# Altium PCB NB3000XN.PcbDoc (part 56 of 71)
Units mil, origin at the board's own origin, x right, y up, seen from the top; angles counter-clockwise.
Board outline 9527.56 x 6929.77 mil, 6 copper layers (Top Layer, GND+SHIELD, MidLayer1, MidLayer2, P2 - 3V3+5V0, Bottom Layer), stack 62.375 mil thick; 832 components, 1027 nets, 4655 pads, 4981 vias.
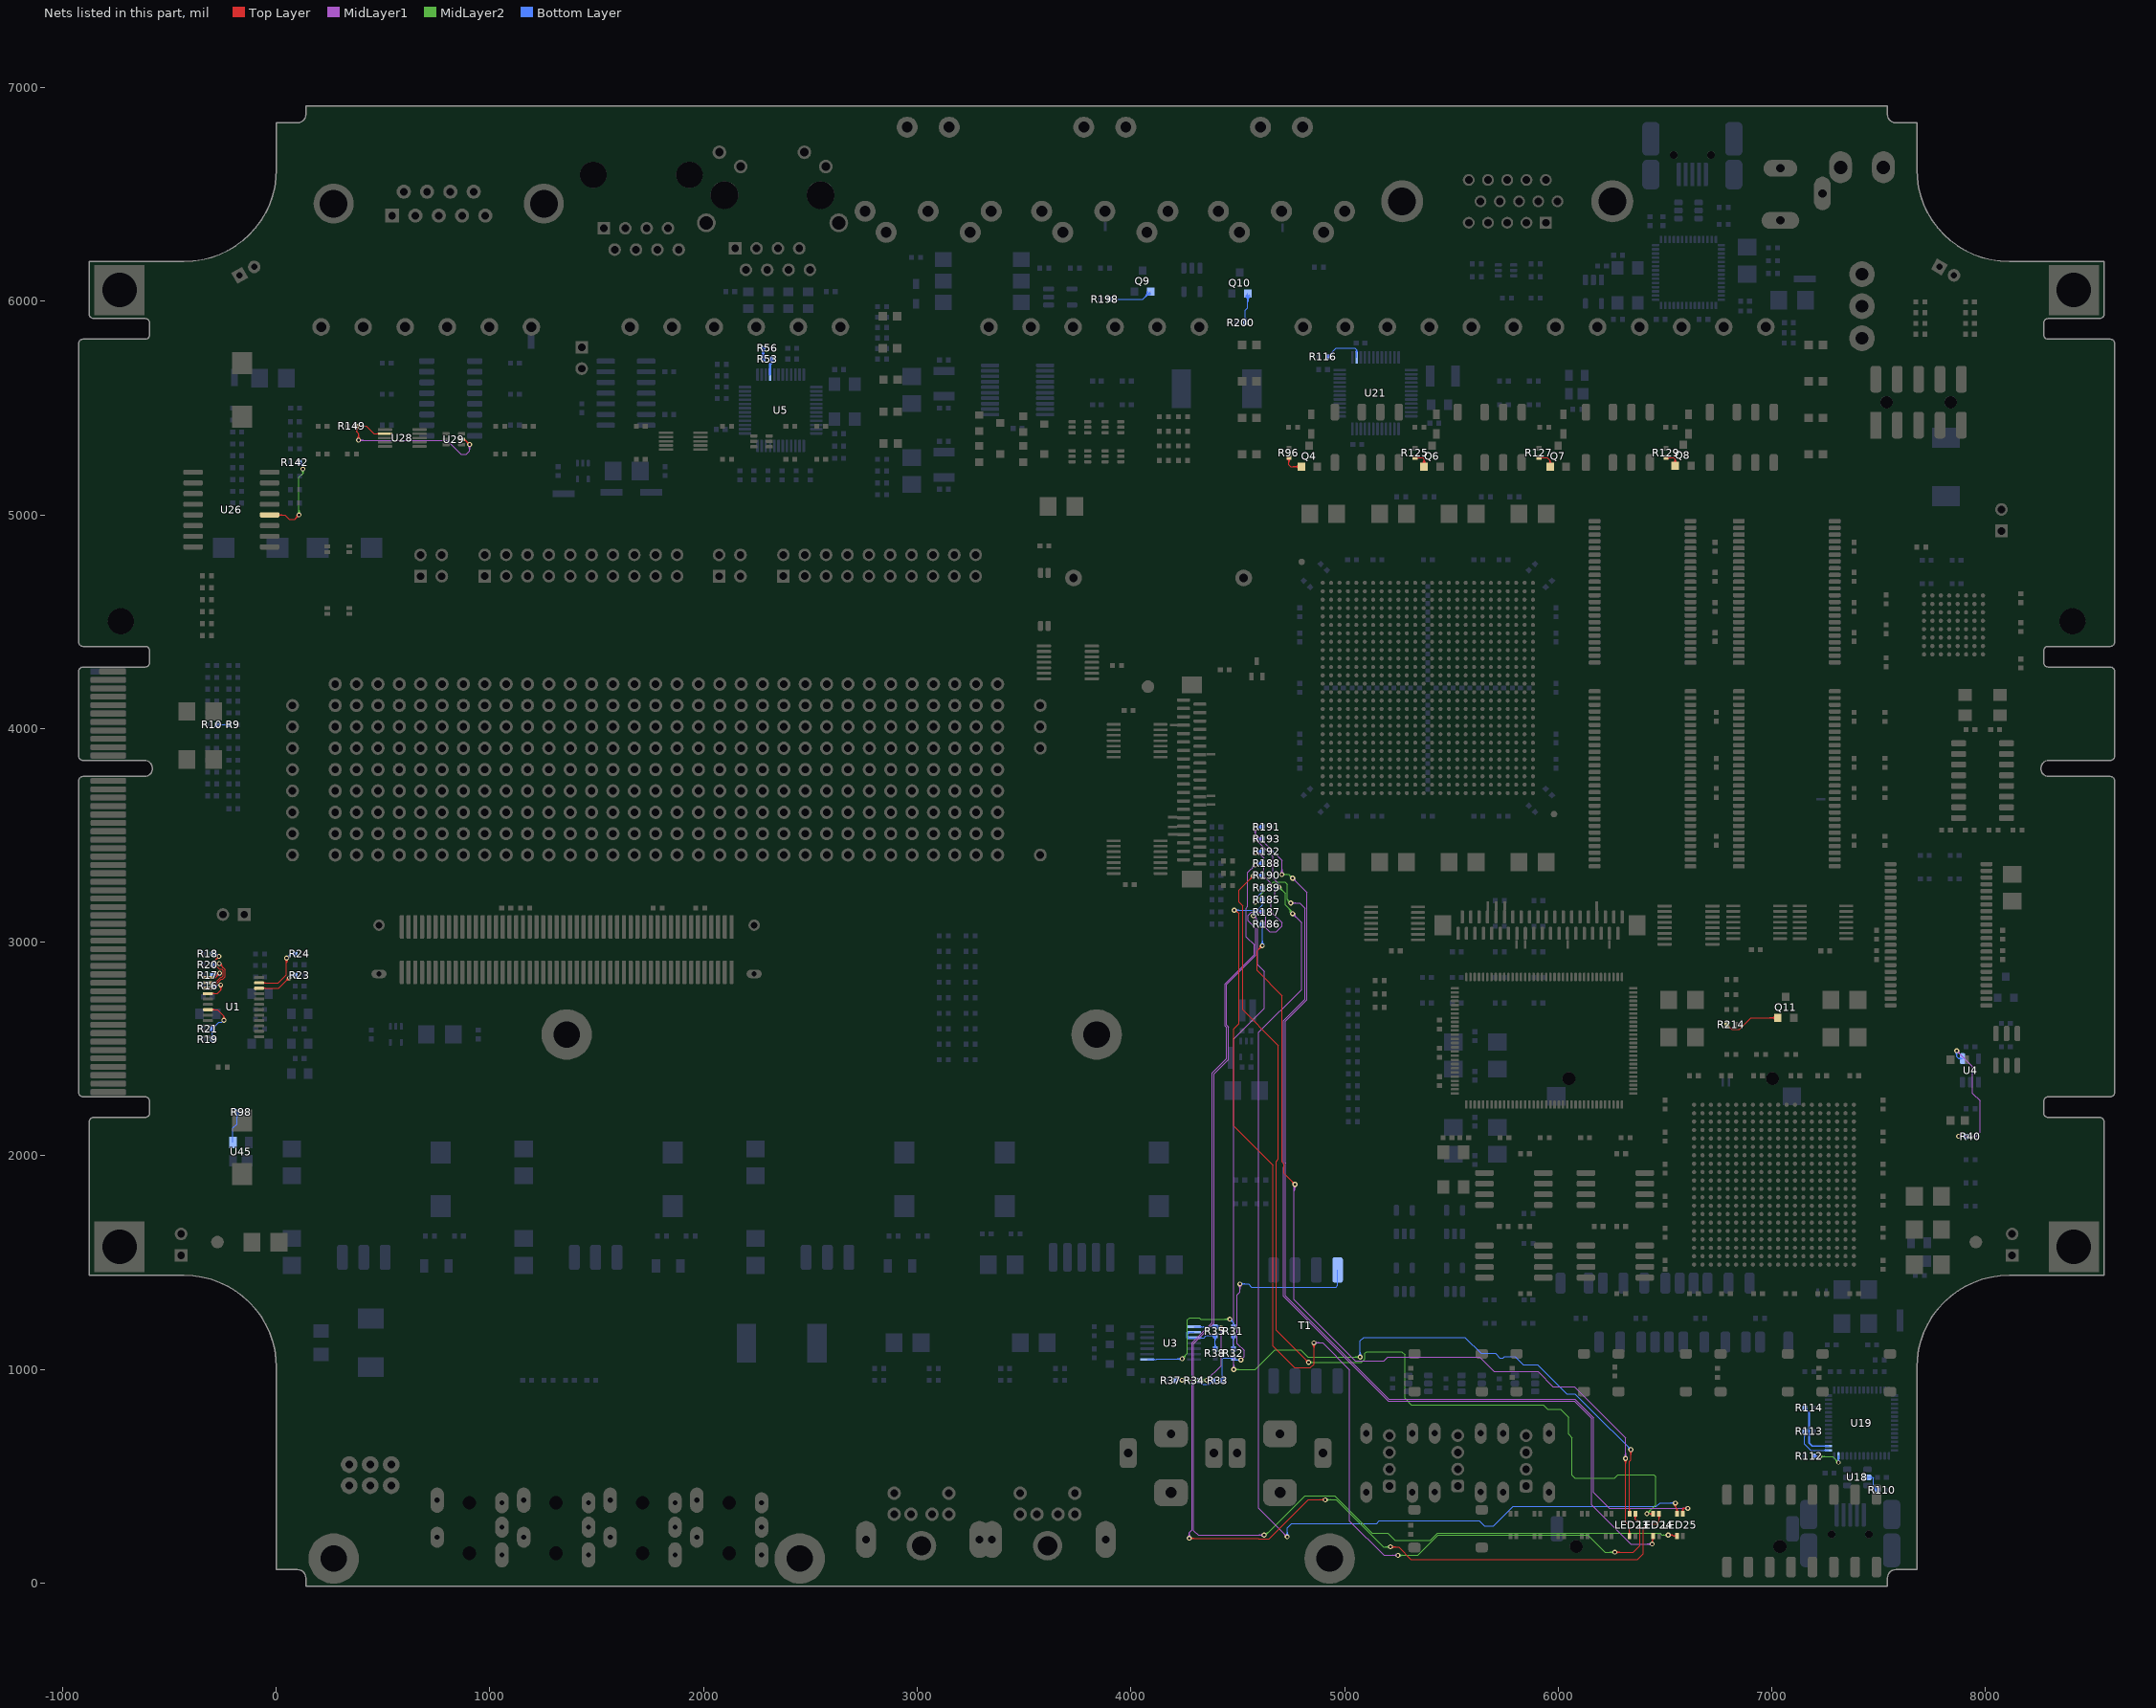
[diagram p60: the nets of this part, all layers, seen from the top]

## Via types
v1: diameter 23, hole 11.81, Top Layer to Bottom Layer, 3672 vias
v2: diameter 26, hole 11.81, Top Layer to Bottom Layer, 461 vias
v3: diameter 19, hole 11.81, Top Layer to Bottom Layer, tented both sides, 396 vias
v4: diameter 23.62, hole 11.81, Top Layer to Bottom Layer, 288 vias
v5: diameter 20, hole 11.81, Top Layer to Bottom Layer, 91 vias
v6: diameter 23, hole 11.81, Top Layer to Bottom Layer, tented both sides, 50 vias
v7: diameter 31, hole 11.81, Top Layer to Bottom Layer, 15 vias
v8: diameter 27.56, hole 11.81, Top Layer to Bottom Layer, tented both sides, 4 vias
v9: diameter 29, hole 11.81, Top Layer to Bottom Layer, 3 vias
v10: diameter 21, hole 11.81, Top Layer to Bottom Layer, 1 vias

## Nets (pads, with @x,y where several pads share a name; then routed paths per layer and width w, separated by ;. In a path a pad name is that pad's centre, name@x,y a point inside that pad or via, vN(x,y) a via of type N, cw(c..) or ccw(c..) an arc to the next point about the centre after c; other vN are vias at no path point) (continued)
NetLED23_1: LED23.1 R185.1 | length 5760.9
  Top Layer w4: v1(4483.52,3150.04) 4490.19,3150.04 4507.19,3133.04 4507.19,2620.02 4481.86,2594.69 4481.86,2138.73 4664.71,1955.87 4664.71,1108.85 4765.19,1008.37 4840.19,1008.37 4856.86,1025.04 v1(4856.86,1125.04) ; v1@4483.55,3148.54 cw(c4483.89,3129.71) 4497.2,3143.03 ; v1@4483.62,3144.54 cw(c4484.12,3116.63) 4503.86,3136.37 ; v1@4493.02,3150.04 ccw(c4499.87,3150.04) 4495.03,3145.2 ; v1@4850.14,1118.32 cw(c4833.92,1102.11) 4856.86,1102.11 cw(c4879.79,1102.11) v1@4863.57,1118.32 ; v1@4852.97,1121.15 cw(c4843.58,1111.76) 4856.86,1111.76 cw(c4870.14,1111.76) v1@4860.75,1121.15 ; v1(6265,145) 6351.86,145 6381.86,175 6381.86,285 6371.86,295 6365,295 6360.79,299.21 LED23.1@6360.79,324.21 ; v1@6268.89,141.11 cw(c6278.28,131.72) 6278.28,145 cw(c6278.28,158.28) v1@6268.89,148.89 ; v1@6271.72,138.28 cw(c6287.93,122.06) 6287.93,145 cw(c6287.93,167.93) v1@6271.72,151.72 ; LED23.1@6355.94,314.44 cw(c6344.23,302.73) 6360.79,302.73 cw(c6377.35,302.73) LED23.1@6365.64,314.44
  MidLayer1 w4: v1(4856.86,1125.04) 4897.92,1125.04 5024.19,998.77 5024.19,290.81 5185,130 v1(5250,130) ; v1@4860.75,1121.15 cw(c4870.14,1111.76) 4870.14,1125.04 cw(c4870.14,1138.32) v1@4860.75,1128.93 ; v1@4863.57,1118.32 cw(c4879.79,1102.11) 4879.79,1125.04 cw(c4879.79,1147.98) v1@4863.57,1131.76 ; v1@5243.28,123.28 ccw(c5227.06,107.06) 5227.06,130 ccw(c5227.06,152.93) v1@5243.28,136.72 ; v1@5246.11,126.11 ccw(c5236.72,116.72) 5236.72,130 ccw(c5236.72,143.28) v1@5246.11,133.89
  MidLayer2 w4: v1(5250,130) 5342.78,130 5438.48,225.71 6139.29,225.71 6220,145 v1(6265,145) ; v1@5253.89,126.11 cw(c5263.28,116.72) 5263.28,130 cw(c5263.28,143.28) v1@5253.89,133.89 ; v1@5256.72,123.28 cw(c5272.93,107.06) 5272.93,130 cw(c5272.93,152.93) v1@5256.72,136.72 ; v1@6258.28,138.28 ccw(c6242.06,122.06) 6242.06,145 ccw(c6242.06,167.93) v1@6258.28,151.72 ; v1@6261.11,141.11 ccw(c6251.72,131.72) 6251.72,145 ccw(c6251.72,158.28) v1@6261.11,148.89
  Bottom Layer w4: v1(4483.52,3150.04) 4590.19,3150.04 4615.19,3175.04 ; v1@4487.41,3146.15 cw(c4496.8,3136.76) 4496.8,3150.04 cw(c4496.8,3163.32) v1@4487.41,3153.93 ; v1@4490.24,3143.32 cw(c4506.46,3127.11) 4506.46,3150.04 cw(c4506.46,3172.98) v1@4490.24,3156.76 ; R185.1@4607.75,3191.19 cw(c4593.87,3175) 4615.19,3175 ; R185.1@4610.36,3194.22 cw(c4601.33,3183.7) 4615.19,3183.7 ; R185.1@4613.82,3198.75 4613.82,3200.04 R185.1@4615.19,3200.04 ; 4615.19,3179.07 cw(c4633.01,3179.07) R185.1@4620.41,3191.67 ; R185.1@4615.19,3198.75 4615.19,3175.04
NetLED23_3: LED23.3 R186.1 | length 4572.2
  Top Layer w4: v1@4605.69,2983.37 cw(c4582.76,2983.37) 4598.97,2967.16 cw(c4615.19,2950.94) v1@4615.19,2973.87 ; v1@4609.69,2983.37 cw(c4596.41,2983.37) 4605.8,2973.99 cw(c4615.19,2964.6) v1@4615.19,2977.87 ; v1(4615.19,2983.37) 4590.19,2958.37 4590.19,2866.71 4706.86,2750.04 4706.86,1971.86 4716.34,1962.38 4716.34,1918.56 v1(4768.19,1866.71) ; v1@4758.69,1866.71 ccw(c4735.76,1866.71) 4751.97,1882.93 ccw(c4768.19,1899.14) v1@4768.19,1876.21 ; v1@4762.69,1866.71 ccw(c4749.41,1866.71) 4758.8,1876.1 ccw(c4768.19,1885.49) v1@4768.19,1872.21 ; v1@6308.47,576.66 cw(c6292.26,560.44) 6315.19,560.44 cw(c6338.13,560.44) v1@6321.91,576.66 ; v1@6311.3,579.49 cw(c6301.91,570.1) 6315.19,570.1 cw(c6328.47,570.1) v1@6319.08,579.49 ; v1(6315.19,583.37) 6315.19,285 6333.59,266.6 LED23.3@6333.59,220.81 ; LED23.3@6328.74,230.58 ccw(c6317.03,242.29) 6333.59,242.29 ccw(c6350.15,242.29) LED23.3@6338.44,230.58
  MidLayer1 w4: v1@4761.47,1859.99 cw(c4753.69,1852.21) 4764.7,1852.21 ; 4764.7,1835.34 cw(c4799.56,1835.34) v1@4774.91,1859.99 ; 4764.7,1844.99 cw(c4789.9,1844.99) v1@4772.08,1862.82 ; 4764.7,1854.65 cw(c4780.25,1854.65) v1@4769.25,1865.65 ; v1(4768.19,1866.71) 4764.7,1863.21 4764.7,1326.14 5049.96,1040.87 5185.69,1040.87 5202.62,1057.81 5632.19,1057.81 5700,990 5905,990 5975,920 6075,920 6314.69,680.31 6314.69,583.87 v1(6315.19,583.37) ; v1@6308.47,590.09 ccw(c6293.46,605.1) 6314.69,605.1 ; v1@6311.3,587.26 ccw(c6303.12,595.45) 6314.69,595.45 ; 6314.69,597.86 ccw(c6329.68,597.86) v1@6319.08,587.26 ; 6314.69,607.52 ccw(c6339.33,607.52) v1@6321.91,590.09
  Bottom Layer w4: R186.1@4607.23,3077.92 cw(c4588.01,3058.7) 4615.19,3058.7 ; v1@4608.47,2990.09 ccw(c4592.26,3006.31) 4615.19,3006.31 ccw(c4638.13,3006.31) v1@4621.91,2990.09 ; R186.1@4610.06,3080.75 cw(c4597.67,3068.36) 4615.19,3068.36 ; v1@4611.3,2987.26 ccw(c4601.91,2996.65) 4615.19,2996.65 ccw(c4628.47,2996.65) v1@4619.08,2987.26 ; R186.1@4613.82,3085 4613.82,3084.51 4615.19,3084.51 v1(4615.19,2983.37) ; 4615.19,3065.32 cw(c4633.01,3065.32) R186.1@4620.41,3077.92
NetLED23_4: LED23.4 R187.1 | length 5308.4
  Top Layer w4: LED23.4@6328.84,333.98 ccw(c6317.81,345.01) 6333.41,345.01 ; LED23.4@6333.41,321.33 6333.41,570 6340.19,576.78 v1(6340.19,625.04) ; 6333.41,346.36 ccw(c6350.92,346.36) LED23.4@6338.54,333.98 ; v1@6333.47,618.32 cw(c6317.26,602.11) 6340.19,602.11 cw(c6363.13,602.11) v1@6346.91,618.32 ; v1@6336.3,621.15 cw(c6326.91,611.76) 6340.19,611.76 cw(c6353.47,611.76) v1@6344.08,621.15
  MidLayer1 w4: v1@4475.14,1006.76 ccw(c4458.92,1022.98) 4481.86,1022.98 ccw(c4504.79,1022.98) v1@4488.57,1006.76 ; v1@4477.97,1003.93 ccw(c4468.58,1013.32) 4481.86,1013.32 ccw(c4495.14,1013.32) v1@4485.75,1003.93 ; v1(4481.86,1000.04) 4481.86,2547.67 4623.86,2689.67 4623.86,2864.04 4593.19,2894.71 4593.19,3104.04 v1(4573.52,3123.71) ; v1@4573.52,3114.21 cw(c4573.52,3091.27) 4589.74,3107.49 cw(c4605.96,3123.71) v1@4583.02,3123.71 ; v1@4573.52,3118.21 cw(c4573.52,3104.93) 4582.91,3114.32 cw(c4592.3,3123.71) v1@4579.02,3123.71
  MidLayer2 w4: v1(4481.86,1000.04) 4583.19,1000.04 4674.86,1091.71 4795.54,1091.71 4828.88,1058.37 v1(5073.52,1058.37) ; v1@4485.75,996.15 cw(c4495.14,986.76) 4495.14,1000.04 cw(c4495.14,1013.32) v1@4485.75,1003.93 ; v1@4488.57,993.32 cw(c4504.79,977.11) 4504.79,1000.04 cw(c4504.79,1022.98) v1@4488.57,1006.76 ; v1@5066.81,1051.66 ccw(c5050.59,1035.44) 5050.59,1058.37 ccw(c5050.59,1081.31) v1@5066.81,1065.09 ; v1@5069.64,1054.49 ccw(c5060.25,1045.1) 5060.25,1058.37 ccw(c5060.25,1071.65) v1@5069.64,1062.26
  Bottom Layer w4: v1(4573.52,3123.71) 4591.69,3141.87 ; v1@4573.52,3129.21 ccw(c4573.52,3142.49) 4582.91,3133.1 ccw(c4592.3,3123.71) v1@4579.02,3123.71 ; v1@4573.52,3133.21 ccw(c4573.52,3156.14) 4589.74,3139.93 ccw(c4605.96,3123.71) v1@4583.02,3123.71 ; R187.1@4607.15,3135.36 ccw(c4591.69,3120.26) 4591.69,3141.87 ; R187.1@4607.15,3148.39 cw(c4591.69,3163.48) 4591.69,3141.87 ; R187.1@4610.01,3138.16 ccw(c4601.19,3129.54) 4601.19,3141.87 ccw(c4601.19,3154.21) R187.1@4610.01,3145.59 ; R187.1@4613.82,3141.88 4591.69,3141.87 ; v1@5066.81,1065.09 ccw(c5050.59,1081.31) 5073.52,1081.31 ccw(c5096.46,1081.31) v1@5080.24,1065.09 ; v1@5069.64,1062.26 ccw(c5060.25,1071.65) 5073.52,1071.65 ccw(c5086.8,1071.65) v1@5077.41,1062.26 ; v1(5073.52,1058.37) 5073.52,1133.52 5090,1150 5564.02,1150 5639.02,1075 5705.79,1075 5727.75,1053.04 5742.25,1053.04 5749.43,1060.22 5798.44,1060.22 5835.66,1023 5903.31,1023 6039.86,886.46 6078.78,886.46 6156.86,808.37 v1(6340.19,625.04) ; v1@6330.69,625.04 ccw(c6307.76,625.04) 6323.97,641.26 ccw(c6340.19,657.48) v1@6340.19,634.54 ; v1@6334.69,625.04 ccw(c6321.41,625.04) 6330.8,634.43 ccw(c6340.19,643.82) v1@6340.19,630.54
NetLED24_1: LED24.1 R188.1 | length 6494.6
  Top Layer w4: v1(4273.52,210) 4595,210 4598.57,206.43 4646.58,206.43 4830.15,390 v4(4910,390) ; v1@4277.41,206.11 cw(c4286.8,196.72) 4286.8,210 cw(c4286.8,223.28) v1@4277.41,213.89 ; v1@4280.24,203.28 cw(c4296.46,187.06) 4296.46,210 cw(c4296.46,232.93) v1@4280.24,216.72 ; v4@4903.06,383.06 ccw(c4886.31,366.31) 4886.31,390 ccw(c4886.31,413.69) v4@4903.06,396.94 ; v4@4905.89,385.89 ccw(c4895.97,375.97) 4895.97,390 ccw(c4895.97,404.03) v4@4905.89,394.11 ; v4(5215,170) 5253.14,170 5311.14,112 6372,112 6398.19,138.19 6398.19,258.19 6417.07,277.07 6458.89,277.07 6472.22,290.4 LED24.1@6472.22,321.33 ; v4@5219.11,165.89 cw(c5229.03,155.97) 5229.03,170 cw(c5229.03,184.03) v4@5219.11,174.11 ; v4@5221.94,163.06 cw(c5238.69,146.31) 5238.69,170 cw(c5238.69,193.69) v4@5221.94,176.94 ; LED24.1@6467.19,314.44 cw(c6455.05,302.3) 6472.22,302.3 ; 6472.22,303.16 cw(c6488.16,303.16) LED24.1@6476.89,314.44
  MidLayer1 w4: v1@4266.81,216.72 ccw(c4250.59,232.93) 4273.52,232.93 ccw(c4296.46,232.93) v1@4280.24,216.72 ; v1@4269.64,213.89 ccw(c4260.25,223.28) 4273.52,223.28 ccw(c4286.8,223.28) v1@4277.41,213.89 ; v1(4273.52,210) 4273.52,236.9 4286,249.37 4286,1124.69 4381.52,1220.21 4381.52,2388 4448.52,2455 4448.52,2600.04 4440.19,2608.37 4440.19,2804.71 4577.19,2941.71 4577.19,2988.04 4540.19,3025.04 4540.19,3159.71 4547.19,3166.71 4547.19,3326.37 v1(4581.86,3361.04) ; v1@4572.36,3361.04 cw(c4549.42,3361.04) 4565.64,3344.82 cw(c4581.86,3328.61) v1@4581.86,3351.54 ; v1@4576.36,3361.04 cw(c4563.08,3361.04) 4572.47,3351.65 cw(c4581.86,3342.26) v1@4581.86,3355.54
  MidLayer2 w4: v4(4910,390) 4961.55,390 5181.55,170 v4(5215,170) ; v4@4914.11,385.89 cw(c4924.03,375.97) 4924.03,390 cw(c4924.03,404.03) v4@4914.11,394.11 ; v4@4916.94,383.06 cw(c4933.69,366.31) 4933.69,390 cw(c4933.69,413.69) v4@4916.94,396.94 ; v4@5208.06,163.06 ccw(c5191.31,146.31) 5191.31,170 ccw(c5191.31,193.69) v4@5208.06,176.94 ; v4@5210.89,165.89 ccw(c5200.97,155.97) 5200.97,170 ccw(c5200.97,184.03) v4@5210.89,174.11
  Bottom Layer w4: v1@4579.73,3362.35 cw(c4592.31,3354.59) 4592.31,3369.37 ; v1(4581.86,3361.04) 4590.19,3369.37 R188.1@4613.82,3369.38 ccw(c4613.82,3341.32) v1@4589.94,3356.05 ; v1@4583.13,3360.25 cw(c4599.48,3350.17) 4599.48,3369.37 ; v1@4586.54,3358.15 cw(c4606.65,3345.74) R188.1@4606.65,3369.37 ; R188.1@4607.23,3362.79 ccw(c4591.32,3346.88) 4591.32,3369.37 ccw(c4591.32,3391.87) R188.1@4607.23,3375.96 ; R188.1@4610.06,3365.61 ccw(c4600.98,3356.53) 4600.98,3369.37 ccw(c4600.98,3382.22) R188.1@4610.06,3373.14
NetLED24_3: LED24.3 R189.1 | length 5102.6
  Top Layer w4: v1@6436.3,187.26 ccw(c6426.91,196.65) 6440.19,196.65 ccw(c6453.47,196.65) v1@6444.08,187.26 ; v1(6440.19,183.37) 6440.19,200 6444.84,204.65 ; LED24.3@6441.7,209.79 cw(c6439.06,204.65) 6444.84,204.65 ; LED24.3@6443.31,222.34 LED24.3@6444.66,223.69 ; LED24.3@6444.84,220.81 6444.84,204.65 ; LED24.3@6447.97,209.79 ccw(c6450.62,204.65) 6444.84,204.65
  MidLayer1 w4: v1(4748.52,3183.37) 4790.52,3183.37 4815.52,3158.37 4815.52,2733.37 4715.19,2633.04 4715.19,1963.52 4716.34,1962.38 4716.34,1947.62 4715.19,1946.48 4715.19,1341.71 5095.75,961.15 5204.9,852 6075.37,852 6156.86,770.52 6156.86,366.71 6340.19,183.37 v1(6440.19,183.37) ; v1@4752.41,3179.49 cw(c4761.8,3170.1) 4761.8,3183.37 cw(c4761.8,3196.65) v1@4752.41,3187.26 ; v1@4755.24,3176.66 cw(c4771.46,3160.44) 4771.46,3183.37 cw(c4771.46,3206.31) v1@4755.24,3190.09 ; v1@6433.47,176.66 ccw(c6417.26,160.44) 6417.26,183.37 ccw(c6417.26,206.31) v1@6433.47,190.09 ; v1@6436.3,179.49 ccw(c6426.91,170.1) 6426.91,183.37 ccw(c6426.91,196.65) v1@6436.3,187.26
  MidLayer2 w4: v1(4581.86,3187.37) 4609.24,3214.75 4609.24,3223.11 4668.5,3282.37 4720.21,3282.37 4731.52,3271.06 4731.52,3200.37 v1(4748.52,3183.37) ; v1@4581.86,3192.87 ccw(c4581.86,3206.15) 4591.25,3196.76 ccw(c4600.64,3187.37) v1@4587.36,3187.37 ; v1@4581.86,3196.87 ccw(c4581.86,3219.81) 4598.07,3203.59 ccw(c4614.29,3187.37) v1@4591.36,3187.37 ; v1@4739.02,3183.37 ccw(c4716.09,3183.37) 4732.31,3199.59 ccw(c4748.52,3215.81) v1@4748.52,3192.87 ; v1@4743.02,3183.37 ccw(c4729.75,3183.37) 4739.14,3192.76 ccw(c4748.52,3202.15) v1@4748.52,3188.87
  Bottom Layer w4: v1@4577.1,3195.6 ccw(c4572.32,3203.85) 4581.86,3203.85 ; v1(4581.86,3187.37) 4581.86,3203.85 ; v1@4586.62,3195.6 cw(c4591.4,3203.85) 4581.86,3203.85 ; R189.1@4608.02,3247.84 cw(c4598.46,3235.81) 4613.82,3235.81 ; R189.1@4613.82,3255.62 4613.82,3235.81 ; R189.1@4619.62,3247.84 ccw(c4629.18,3235.81) 4613.82,3235.81 ; 4581.86,3203.85 4613.82,3235.81
NetLED24_4: LED24.4 R190.1 | length 5308.6
  Top Layer w4: v1@4564.02,3310.04 cw(c4541.09,3310.04) 4557.31,3293.82 cw(c4573.52,3277.61) v1@4573.52,3300.54 ; v1@4568.02,3310.04 cw(c4554.75,3310.04) 4564.14,3300.65 cw(c4573.52,3291.26) v1@4573.52,3304.54 ; v1(4573.52,3310.04) 4506.52,3243.04 4506.52,3188.04 4523.52,3171.04 4523.52,2683.37 4669.72,2537.18 4690.52,2516.37 4690.52,1984.48 4680.71,1974.66 4680.71,1184.52 v1(4831.86,1033.37) ; v1@4822.36,1033.37 ccw(c4799.42,1033.37) 4815.64,1049.59 ccw(c4831.86,1065.81) v1@4831.86,1042.87 ; v1@4826.36,1033.37 ccw(c4813.08,1033.37) 4822.47,1042.76 ccw(c4831.86,1052.15) v1@4831.86,1038.87 ; v1(6415.19,325.04) 6429.96,325.04 6430.79,324.21 ; LED24.4@6439.55,319.96 ccw(c6430.79,313.05) 6430.79,324.21 ; LED24.4@6439.55,328.45 cw(c6430.79,335.36) 6430.79,324.21 ; LED24.4@6444.94,324.21 6430.79,324.21
  MidLayer2 w4: v1(4831.86,1033.37) 5080,1033.37 5095,1048.37 5095,1075 5103.37,1083.37 5267.56,1083.37 5282.19,1068.75 5282.19,864.67 5311.98,834.87 5930.13,834.87 5950,815 6010,815 6048.65,776.35 6048.65,696.54 6065.19,680 6065.19,505.04 6078.52,491.71 6263.86,491.71 6280.52,508.37 6446.86,508.37 6456.86,498.37 6456.86,366.71 v1(6415.19,325.04) ; v1@4835.75,1029.49 cw(c4845.14,1020.1) 4845.14,1033.37 cw(c4845.14,1046.65) v1@4835.75,1037.26 ; v1@4838.57,1026.66 cw(c4854.79,1010.44) 4854.79,1033.37 cw(c4854.79,1056.31) v1@4838.57,1040.09 ; 6424.58,334.43 cw(c6415.19,343.82) 6415.19,330.54 ccw(c6415.19,343.82) 6424.58,334.43 ; 6424.58,334.43 ccw(c6433.97,325.04) 6420.69,325.04 cw(c6433.97,325.04) 6424.58,334.43 ; 6431.41,341.26 cw(c6415.19,357.48) 6415.19,334.54 ccw(c6415.19,357.48) 6431.41,341.26 ; 6431.41,341.26 ccw(c6447.63,325.04) 6424.69,325.04 cw(c6447.63,325.04) 6431.41,341.26
  Bottom Layer w4: v1(4573.52,3310.04) 4580.19,3310.04 4582.65,3312.5 R190.1@4613.82,3312.5 ; v1@4577.41,3306.15 cw(c4592.74,3290.83) 4592.74,3312.5 ; v1@4580.24,3303.32 cw(c4602.4,3281.17) 4602.4,3312.5 ; v1@4580.24,3316.76 ccw(c4590.52,3327.04) 4590.52,3312.5 ; R190.1@4607.23,3305.91 ccw(c4591.32,3290) 4591.32,3312.5 ccw(c4591.32,3335) R190.1@4607.23,3319.09 ; R190.1@4610.06,3308.74 ccw(c4600.98,3299.66) 4600.98,3312.5 ccw(c4600.98,3325.34) R190.1@4610.06,3316.26
NetLED25_1: LED25.1 R191.1 | length 5492.9
  Top Layer w4: LED25.1@6578.43,333.98 ccw(c6566.73,345.69) 6583.28,345.69 ccw(c6599.84,345.69) LED25.1@6588.13,333.98 ; LED25.1@6583.28,324.21 6583.28,348.19 6585.13,350.04 ; v1@6599.88,343.59 ccw(c6585.13,329.95) 6585.13,350.04 ; v1@6599.88,356.49 cw(c6585.13,370.13) 6585.13,350.04 ; v1@6602.82,346.31 ccw(c6594.28,338.41) 6594.28,350.04 ccw(c6594.28,361.67) v1@6602.82,353.78 ; v1(6606.86,350.04) 6585.13,350.04
  MidLayer1 w4: v1@4575.14,3525.66 cw(c4558.92,3509.44) 4581.86,3509.44 cw(c4604.79,3509.44) v1@4588.57,3525.66 ; v1@4577.97,3528.49 cw(c4568.58,3519.1) 4581.86,3519.1 cw(c4595.14,3519.1) v1@4585.75,3528.49 ; v1(4581.86,3532.37) 4581.86,3508.37 4706.86,3383.37 v1(4706.86,3316.71) ; v1@4700.14,3323.43 ccw(c4683.92,3339.64) 4706.86,3339.64 ccw(c4729.79,3339.64) v1@4713.57,3323.43 ; v1@4702.97,3320.6 ccw(c4693.58,3329.99) 4706.86,3329.99 ccw(c4720.14,3329.99) v1@4710.75,3320.6 ; v1@4756.86,3290.54 cw(c4756.86,3267.61) 4773.07,3283.82 cw(c4789.29,3300.04) v1@4766.36,3300.04 ; v1@4756.86,3294.54 cw(c4756.86,3281.26) 4766.25,3290.65 cw(c4775.64,3300.04) v1@4762.36,3300.04 ; v1(4756.86,3300.04) 4823.52,3233.37 4823.52,2730.06 4723.19,2629.73 4723.19,1966.84 4724.34,1965.69 4724.34,1944.31 4723.19,1943.16 4723.19,1345.02 5208.21,860 6078.69,860 6165.19,773.5 6165.19,425.04 6240.19,350.04 v1(6606.86,350.04) ; v1@6600.14,343.32 ccw(c6583.92,327.11) 6583.92,350.04 ccw(c6583.92,372.98) v1@6600.14,356.76 ; v1@6602.97,346.15 ccw(c6593.58,336.76) 6593.58,350.04 ccw(c6593.58,363.32) v1@6602.97,353.93
  MidLayer2 w4: v1(4706.86,3316.71) 4740.19,3316.71 v1(4756.86,3300.04) ; v1@4710.75,3312.82 cw(c4720.14,3303.43) 4720.14,3316.71 cw(c4720.14,3329.99) v1@4710.75,3320.6 ; v1@4713.57,3309.99 cw(c4729.79,3293.77) 4729.79,3316.71 cw(c4729.79,3339.64) v1@4713.57,3323.43 ; v1@4747.36,3300.04 ccw(c4724.42,3300.04) 4740.64,3316.26 ccw(c4756.86,3332.48) v1@4756.86,3309.54 ; v1@4751.36,3300.04 ccw(c4738.08,3300.04) 4747.47,3309.43 ccw(c4756.86,3318.82) v1@4756.86,3305.54
  Bottom Layer w4: v1@4579.78,3533.76 cw(c4591.42,3526.01) 4591.42,3540 ; v1(4581.86,3532.37) 4581.86,3533.37 4588.48,3540 R191.1@4613.82,3540 ccw(c4613.82,3511.11) v1@4589.77,3527.11 ; v1@4583.11,3531.54 cw(c4598.89,3521.05) 4598.89,3540 ; v1@4586.44,3529.33 cw(c4606.35,3516.08) R191.1@4606.35,3540 ; R191.1@4607.23,3533.41 ccw(c4591.32,3517.5) 4591.32,3540 ccw(c4591.32,3562.5) R191.1@4607.23,3546.59 ; R191.1@4610.06,3536.24 ccw(c4600.98,3527.16) 4600.98,3540 ccw(c4600.98,3552.84) R191.1@4610.06,3543.76
NetLED25_3: LED25.3 R192.1 | length 6560.1
  Top Layer w4: v1(6515.19,225.04) 6535,225.04 ; v1@6522.6,219.09 cw(c6535,209.14) 6535,225.04 ; v1@6522.6,230.99 ccw(c6535,240.94) 6535,225.04 ; 6536.35,223.69 6535,225.04 ; LED25.3@6551.23,215.96 ccw(c6539.53,204.25) 6539.53,220.81 ccw(c6539.53,237.36) LED25.3@6551.23,225.66 ; LED25.3@6556.08,220.81 6539.23,220.81 6535,225.04
  MidLayer1 w4: v1(4581.86,3418.71) 4598.52,3418.71 ; v1@4590.03,3413.87 cw(c4598.52,3408.84) 4598.52,3418.71 ; v1@4590.03,3423.55 ccw(c4598.52,3428.58) 4598.52,3418.71 ; v1@4616.81,218.32 ccw(c4600.59,202.11) 4600.59,225.04 ccw(c4600.59,247.98) v1@4616.81,231.76 ; v1@4619.64,221.15 ccw(c4610.25,211.76) 4610.25,225.04 ccw(c4610.25,238.32) v1@4619.64,228.93 ; v1(4623.52,225.04) 4315,225.04 4294,246.04 4294,970 4294,1121.37 4389.52,1216.9 4389.52,2384.69 4456.86,2452.02 4456.86,2603.02 4448.52,2611.35 4448.52,2801.73 4585.19,2938.39 4585.19,3063.37 4548.52,3100.04 4548.52,3125.04 4565.19,3141.71 4615.19,3141.71 4631.86,3125.04 4631.86,3066.71 4648.52,3050.04 4681.86,3050.04 4706.86,3075.04 4706.86,3091.71 4656.86,3141.71 4656.86,3200.04 4673.52,3216.71 4673.52,3258.37 4623.52,3308.37 4623.52,3393.71 4598.52,3418.71
  MidLayer2 w4: v1(4623.52,225.04) 4631.86,225.04 4814.63,407.81 4955.05,407.81 5127.67,235.19 5202.06,235.19 5236.88,200.37 5401.84,200.37 5435.17,233.71 6476.33,233.71 6485,225.04 v1(6515.19,225.04) ; v1@4623.52,226.54 ccw(c4623.52,250.28) 4640.31,233.49 ; v1@4623.52,230.54 ccw(c4623.52,263.94) 4647.14,240.32 ; v1@4623.52,234.54 ccw(c4623.52,277.59) 4653.97,247.15 ; v1@6508.47,218.32 ccw(c6492.26,202.11) 6492.26,225.04 ccw(c6492.26,247.98) v1@6508.47,231.76 ; v1@6511.3,221.15 ccw(c6501.91,211.76) 6501.91,225.04 ccw(c6501.91,238.32) v1@6511.3,228.93
  Bottom Layer w4: v1(4581.86,3418.71) 4588.19,3425.04 R192.1@4613.82,3425.04 ; v1@4583.05,3417.8 cw(c4597.67,3406.67) 4597.67,3425.04 ; v1@4586.23,3415.38 cw(c4605.74,3400.52) R192.1@4605.74,3425.04 ; v1@4589.42,3412.95 cw(c4613.82,3394.37) R192.1@4613.82,3425.04 ; v1@4589.59,3425.04 ccw(c4589.59,3449.99) R192.1@4607.23,3432.35 ; 4593.05,3425.04 cw(c4593.05,3404.99) R192.1@4607.23,3419.17 ; 4599.25,3425.04 ccw(c4599.25,3440.33) R192.1@4610.06,3429.52 ; R192.1@4613.82,3426.25 R192.1@4613.82,3425.04
NetLED25_4: LED25.4 R193.1 | length 6150.4
  Top Layer w4: v1@6543.2,366.51 cw(c6536.41,356.48) 6548.52,356.48 ; v1(6548.52,374.37) 6548.52,356.48 ; LED25.4@6551.33,333.98 ccw(c6539.63,345.69) 6556.18,345.69 ccw(c6572.74,345.69) LED25.4@6561.03,333.98 ; v1@6553.85,366.51 ccw(c6560.63,356.48) 6548.52,356.48 ; LED25.4@6556.18,324.21 6556.18,348.82 6548.52,356.48 ; LED25.4@6556.86,321.33 LED25.4@6556.86,324.21
  MidLayer1 w4: v1@4581.86,3473.87 cw(c4581.86,3450.94) 4598.07,3467.16 cw(c4614.29,3483.37) v1@4591.36,3483.37 ; v1@4581.86,3477.87 cw(c4581.86,3464.6) 4591.25,3473.99 cw(c4600.64,3483.37) v1@4587.36,3483.37 ; v1(4581.86,3483.37) 4665.19,3400.04 4665.19,3300.04 4692.86,3272.37 v1(4692.86,3258.37) ; v1@4722.36,216.71 ccw(c4699.42,216.71) 4715.64,232.93 ccw(c4731.86,249.14) v1@4731.86,226.21 ; v1@4726.36,216.71 ccw(c4713.08,216.71) 4722.47,226.1 ccw(c4731.86,235.49) v1@4731.86,222.21 ; v1(4731.86,216.71) 4632.6,315.97 4598.52,350.04 4598.52,2578.02 4799.52,2779.02 4799.52,3090.71 v1(4756.86,3133.37) ; v1@4756.86,3123.87 cw(c4756.86,3100.94) 4773.07,3117.16 cw(c4789.29,3133.37) v1@4766.36,3133.37 ; v1@4756.86,3127.87 cw(c4756.86,3114.6) 4766.25,3123.99 cw(c4775.64,3133.37) v1@4762.36,3133.37
  MidLayer2 w4: v1@4692.86,3248.87 cw(c4692.86,3225.94) 4709.07,3242.16 cw(c4725.29,3258.37) v1@4702.36,3258.37 ; v1@4692.86,3252.87 cw(c4692.86,3239.6) 4702.25,3248.99 cw(c4711.64,3258.37) v1@4698.36,3258.37 ; v1(4692.86,3258.37) 4723.52,3227.71 4723.52,3175.04 4756.86,3141.71 v1(4756.86,3133.37) ; 4734.75,3163.82 cw(c4704.3,3133.37) v1@4747.36,3133.37 ; 4741.58,3156.99 cw(c4717.96,3133.37) v1@4751.36,3133.37 ; 4748.4,3150.16 cw(c4731.62,3133.37) v1@4755.36,3133.37
  Bottom Layer w4: v1(4581.86,3483.37) 4613.15,3483.37 4613.61,3482.92 4613.82,3482.71 4613.82,3482.63 R193.1@4613.82,3483.12 ; v1@4585.75,3479.49 cw(c4595.14,3470.1) 4595.14,3483.37 cw(c4595.14,3496.65) v1@4585.75,3487.26 ; v1@4588.57,3476.66 cw(c4604.79,3460.44) 4604.79,3483.37 cw(c4604.79,3506.31) v1@4588.57,3490.09 ; v1@4590.74,3483.37 ccw(c4590.74,3506.7) R193.1@4607.23,3490.21 ; v1@4591.91,3483.37 cw(c4591.91,3461.7) R193.1@4607.23,3477.03 ; 4600.39,3483.37 ccw(c4600.39,3497.04) R193.1@4610.06,3487.38 ; 4601.56,3483.37 cw(c4601.56,3471.36) R193.1@4610.06,3479.86 ; v1@4725.14,223.43 ccw(c4708.92,239.64) 4731.86,239.64 ccw(c4754.79,239.64) v1@4738.57,223.43 ; v1@4727.97,220.6 ccw(c4718.58,229.99) 4731.86,229.99 ccw(c4745.14,229.99) v1@4735.75,220.6 ; v1(4731.86,216.71) 4731.86,258.4 4752.64,279.19 5150.69,279.19 5163.21,291.71 5630,291.71 5655,266.71 5698.52,266.71 5790.19,358.37 6460,358.37 6476,374.37 v1(6548.52,374.37) ; 6525.59,374.37 cw(c6525.59,351.44) 6541.81,367.66 ccw(c6525.59,351.44) 6525.59,374.37 ; 6525.59,374.37 ccw(c6525.59,397.31) 6541.81,381.09 cw(c6525.59,397.31) 6525.59,374.37 ; 6535.25,374.37 cw(c6535.25,361.1) 6544.64,370.49 ccw(c6535.25,361.1) 6535.25,374.37 ; 6535.25,374.37 ccw(c6535.25,387.65) 6544.64,378.26 cw(c6535.25,387.65) 6535.25,374.37
NetQ4_1: Q4.1 R96.2 | length 284.7
  Top Layer w4: R96.2@4733.41,5262.23 cw(c4717.5,5246.32) 4740,5246.32 cw(c4762.5,5246.32) R96.2@4746.59,5262.23 ; R96.2@4736.24,5265.06 cw(c4727.16,5255.98) 4740,5255.98 cw(c4752.84,5255.98) R96.2@4743.76,5265.06 ; R96.2@4740,5268.82 4740,5233.79 4748,5225.79 Q4.1@4797.6,5225.79 ; Q4.1@4786.49,5214.67 ccw(c4759.66,5187.85) 4759.66,5225.79 ccw(c4759.65,5263.73) Q4.1@4786.49,5236.9 ; Q4.1@4789.31,5217.5 ccw(c4769.31,5197.5) 4769.31,5225.79 ccw(c4769.31,5254.07) Q4.1@4789.31,5234.07 ; Q4.1@4792.14,5220.33 ccw(c4778.97,5207.16) 4778.97,5225.79 ccw(c4778.97,5244.42) Q4.1@4792.14,5231.24
NetQ6_1: Q6.1 R125.2 | length 231.7
  Top Layer w4: R125.2@5330,5268.82 5366.18,5268.82 5372.6,5262.4 ; R125.2@5334.25,5265.06 cw(c5343.33,5255.98) 5343.33,5268.82 cw(c5343.33,5281.66) R125.2@5334.25,5272.58 ; R125.2@5337.08,5262.23 cw(c5352.99,5246.32) 5352.99,5268.82 cw(c5352.99,5291.32) R125.2@5337.08,5275.41 ; Q6.1@5362,5238.38 ccw(c5340.07,5262.4) 5372.6,5262.4 ; Q6.1@5364.7,5235.42 ccw(c5348.35,5253.33) 5372.6,5253.33 ccw(c5396.85,5253.33) Q6.1@5380.5,5235.42 ; Q6.1@5372.6,5225.79 5372.6,5262.4 ; Q6.1@5383.19,5238.38 cw(c5405.12,5262.4) 5372.6,5262.4
NetQ7_1: Q7.1 R127.2 | length 205.1
  Top Layer w4: R127.2@5910,5268.82 5948.78,5268.82 5962.6,5255 Q7.1@5962.6,5225.79 ; R127.2@5914.25,5265.06 cw(c5923.33,5255.98) 5923.33,5268.82 cw(c5923.33,5281.66) R127.2@5914.25,5272.58 ; R127.2@5917.08,5262.23 cw(c5932.99,5246.32) 5932.99,5268.82 cw(c5932.99,5291.32) R127.2@5917.08,5275.41 ; Q7.1@5954.32,5240.13 ccw(c5945.11,5255) 5962.6,5255 ccw(c5980.09,5255) Q7.1@5970.88,5240.13 ; Q7.1@5956.43,5236.73 ccw(c5949.56,5247.81) 5962.6,5247.81 ccw(c5975.64,5247.81) Q7.1@5968.77,5236.73
NetQ8_1: Q8.1 R129.2 | length 197.2
  Top Layer w4: R129.2@6505,5268.82 6539.6,5268.82 6547.6,5260.82 ; R129.2@6509.25,5265.06 cw(c6518.33,5255.98) 6518.33,5268.82 cw(c6518.33,5281.66) R129.2@6509.25,5272.58 ; R129.2@6512.08,5262.23 cw(c6527.99,5246.32) 6527.99,5268.82 cw(c6527.99,5291.32) R129.2@6512.08,5275.41 ; Q8.1@6539,5244.93 ccw(c6528.62,5260.82) 6547.6,5260.82 ; Q8.1@6541.19,5241.58 ccw(c6533.45,5253.43) 6547.6,5253.43 ccw(c6561.75,5253.42) Q8.1@6554.01,5241.58 ; Q8.1@6547.6,5230.79 6547.6,5260.82 ; Q8.1@6556.2,5244.93 cw(c6566.58,5260.82) 6547.6,5260.82
NetQ9_1: Q9.1 R198.2 | length 382.1
  Bottom Layer w4: R198.2@3901.18,6010 4056.61,6010 Q9.1@4092.4,6045.79 ; R198.2@3904.94,6006.24 cw(c3914.02,5997.16) 3914.02,6010 cw(c3914.02,6022.84) R198.2@3904.94,6013.76 ; R198.2@3907.77,6003.41 cw(c3923.68,5987.5) 3923.68,6010 cw(c3923.68,6032.5) R198.2@3907.77,6016.59 ; 4063.89,6017.28 cw(c4092.4,5988.77) Q9.1@4092.4,6029.09 ; 4066.27,6019.65 ccw(c4041.12,6044.8) Q9.1@4076.69,6044.8 ; 4070.72,6024.11 cw(c4092.4,6002.42) Q9.1@4092.4,6033.09 ; 4073.1,6026.48 ccw(c4054.78,6044.8) Q9.1@4080.69,6044.8 ; Q9.1@4077.55,6030.93 cw(c4092.4,6016.08) Q9.1@4092.4,6037.09
NetQ10_1: Q10.1 R200.2 | length 329.2
  Bottom Layer w4: R200.2@4529.59,5907.08 ccw(c4513.68,5922.99) 4536.18,5922.99 ccw(c4558.68,5922.99) R200.2@4542.77,5907.08 ; R200.2@4532.42,5904.25 ccw(c4523.34,5913.33) 4536.18,5913.33 ccw(c4549.02,5913.33) R200.2@4539.94,5904.25 ; R200.2@4536.18,5900 4536.18,5958.37 4547.4,5969.6 Q10.1@4547.4,6035.79 ; Q10.1@4536.29,6023.69 cw(c4509.46,5996.86) 4547.4,5996.86 cw(c4585.34,5996.86) Q10.1@4558.51,6023.69 ; Q10.1@4539.12,6026.52 cw(c4519.11,6006.52) 4547.4,6006.52 cw(c4575.69,6006.52) Q10.1@4555.69,6026.52 ; Q10.1@4541.95,6029.35 cw(c4528.77,6016.17) 4547.4,6016.17 cw(c4566.03,6016.18) Q10.1@4552.86,6029.35
NetQ11_1: Q11.1 R214.1 | length 459.6
  Top Layer w4: R214.1@6788.82,2605.19 cw(c6788.82,2581.5) 6805.57,2598.25 ; R214.1@6788.82,2609.19 cw(c6788.82,2595.16) R214.1@6798.74,2605.08 ; R214.1@6788.82,2615 6812.11,2591.71 6848.52,2591.71 6902.6,2645.79 Q11.1@7027.6,2645.79 ; R214.1@6794.14,2614.51 ccw(c6805.79,2614.51) R214.1@6797.55,2606.27 ; R214.1@6798.14,2614.51 ccw(c6819.45,2614.51) 6804.38,2599.44 ; Q11.1@7016.49,2634.67 ccw(c6989.66,2607.85) 6989.66,2645.79 ccw(c6989.65,2683.73) Q11.1@7016.49,2656.9 ; Q11.1@7019.31,2637.5 ccw(c6999.31,2617.5) 6999.31,2645.79 ccw(c6999.31,2674.07) Q11.1@7019.31,2654.07 ; Q11.1@7022.14,2640.33 ccw(c7008.97,2627.16) 7008.97,2645.79 ccw(c7008.97,2664.42) Q11.1@7022.14,2651.24
NetR9_2: R9.2 R10.1 | length 168.7
  Bottom Layer w4: R10.1@-278.82,4017.73 R9.2@-221.18,4017.73 ; R10.1@-275.06,4013.97 cw(c-265.98,4004.89) -265.98,4017.73 cw(c-265.98,4030.57) R10.1@-275.06,4021.49 ; R10.1@-272.23,4011.14 cw(c-256.32,3995.23) -256.32,4017.73 cw(c-256.32,4040.23) R10.1@-272.23,4024.32 ; R9.2@-227.77,4011.14 ccw(c-243.68,3995.23) -243.68,4017.73 ccw(c-243.68,4040.23) R9.2@-227.77,4024.32 ; R9.2@-224.94,4013.97 ccw(c-234.02,4004.89) -234.02,4017.73 ccw(c-234.02,4030.57) R9.2@-224.94,4021.49
NetR16_1: R16.1 U1.4 | length 234
  Top Layer w4: U1.4@-320,2759.41 -275.59,2759.41 -260,2775 -260,2799.85 v1(-259.81,2800.04) ; U1.4@-300.26,2755.81 cw(c-291.58,2747.13) -291.58,2759.41 cw(c-291.58,2771.69) U1.4@-300.26,2763.01 ; v1@-266.53,2793.32 cw(c-282.29,2777.56) -260,2777.56 ; v1@-263.7,2796.15 cw(c-272.63,2787.22) -260,2787.22 ; -260,2776.65 cw(c-236.42,2776.65) v1@-253.09,2793.32 ; -260,2786.3 cw(c-246.07,2786.3) v1@-255.92,2796.15
  Bottom Layer w4: R16.1@-298.82,2795 -280.48,2795 ; R16.1@-291.29,2789.5 cw(c-280.48,2781.61) -280.48,2795 ; R16.1@-291.29,2800.5 ccw(c-280.48,2808.39) -280.48,2795 ; v1(-259.81,2800.04) -275.43,2800.04 -280.48,2795
NetR17_1: R17.1 U1.1 | length 356.2
  Top Layer w4: U1.1@-320,2835 -285,2835 v1(-265,2855) v1@-264.77,2855 ; U1.1@-300.26,2831.4 cw(c-291.58,2822.72) -291.58,2835 cw(c-291.58,2847.28) U1.1@-300.26,2838.6 ; v1@-274.5,2855 cw(c-297.44,2855) -281.22,2838.78 cw(c-265,2822.56) v1@-265,2845.5 ; v1@-270.5,2855 cw(c-283.78,2855) -274.39,2845.61 cw(c-265,2836.22) v1@-265,2849.5
  Bottom Layer w4: R17.1@-295.06,2841.24 cw(c-285.98,2832.16) -285.98,2845 cw(c-285.98,2857.84) R17.1@-295.06,2848.76 ; R17.1@-292.23,2838.41 cw(c-276.32,2822.5) -276.32,2845 cw(c-276.32,2867.5) R17.1@-292.23,2851.59 ; R17.1@-291.88,2845 ccw(c-291.88,2870.56) v1@-269.76,2857.76 ; -284.94,2845 ccw(c-284.94,2866.54) v1@-266.3,2855.75 ; -278.01,2845 ccw(c-278.01,2862.53) v1@-262.84,2853.75 ; v1@-273.22,2859.76 cw(c-298.82,2874.57) R17.1@-298.82,2845 -265,2845 -264.85,2845 -259.93,2849.93 -259.81,2850.04 -264.77,2855 v1(-265,2855) ; -271.07,2845 ccw(c-271.07,2858.51) v1@-259.37,2851.74
NetR18_2: R18.2 U1.2 | length 346.2
  Top Layer w4: U1.2@-320,2809.8 -286.11,2809.8 -260.16,2835.75 -254.25,2835.75 -247.5,2842.5 -247.5,2868.23 -254.27,2875 -266.18,2875 -283.98,2892.79 -283.98,2917.54 ; U1.2@-300.26,2806.21 cw(c-291.58,2797.52) -291.58,2809.8 cw(c-291.58,2822.08) U1.2@-300.26,2813.4 ; v1@-277.31,2933.69 cw(c-300.07,2933.63) -283.98,2917.54 ; v1@-273.31,2933.7 cw(c-286.48,2933.67) -277.17,2924.35 cw(c-267.85,2915.03) v1@-267.82,2928.21 ; v1@-267.83,2924.21 ccw(c-267.88,2901.45) -283.98,2917.54 ; v1(-267.81,2933.71) -283.98,2917.54
  Bottom Layer w4: R18.2@-298.82,2945 -279.1,2945 ; R18.2@-291.62,2939.08 cw(c-279.1,2928.8) -279.1,2945 ; R18.2@-291.62,2950.92 ccw(c-279.1,2961.2) -279.1,2945 ; v1(-267.81,2933.71) -279.1,2945
NetR19_1: R19.1 R21.2 U1.7 | length 458.8
  Top Layer w4: U1.7@-320,2683.82 -273.82,2683.82 -245,2655 v1(-245,2635) ; U1.7@-300.26,2680.22 cw(c-291.58,2671.54) -291.58,2683.82 cw(c-291.58,2696.1) U1.7@-300.26,2687.42 ; v1@-251,2642.36 ccw(c-261.3,2655) -245,2655 ccw(c-228.7,2655) v1@-239,2642.36 ; v1@-248.47,2639.26 ccw(c-254.44,2646.58) -245,2646.58 ccw(c-235.56,2646.58) v1@-241.53,2639.26
  Bottom Layer w4: R19.1@-305.41,2552.08 ccw(c-321.32,2567.99) -298.82,2567.99 ccw(c-276.32,2567.99) R19.1@-292.23,2552.08 ; R21.2@-305.41,2587.92 cw(c-321.32,2572.01) -298.82,2572.01 cw(c-276.32,2572.01) R21.2@-292.23,2587.92 ; R19.1@-302.58,2549.25 ccw(c-311.66,2558.33) -298.82,2558.33 ccw(c-285.98,2558.33) R19.1@-295.06,2549.25 ; R21.2@-302.58,2590.75 cw(c-311.66,2581.67) -298.82,2581.67 cw(c-285.98,2581.67) R21.2@-295.06,2590.75 ; R19.1@-298.82,2545 R21.2@-298.82,2595 -268.82,2625 -255,2625 v1(-245,2635) ; R21.2@-298.82,2600.81 ccw(c-298.82,2614.84) R21.2@-288.9,2604.92 ; R21.2@-298.82,2604.81 ccw(c-298.82,2628.5) -282.07,2611.75 ; R21.2@-293.5,2595.49 cw(c-281.85,2595.49) R21.2@-290.09,2603.73 ; R21.2@-289.5,2595.49 cw(c-268.19,2595.49) -283.26,2610.56
NetR20_2: R20.2 U1.3 | length 413.4
  Top Layer w4: U1.3@-300.26,2781.01 cw(c-290.63,2771.38) -290.63,2785 ; U1.3@-300.26,2788.2 ccw(c-292.53,2795.94) -292.53,2785 ; v1@-266.48,2890.54 cw(c-266.48,2871.29) -252.86,2884.9 ; v1(-266.48,2900.04) -266.48,2898.52 -239.5,2871.54 -239.5,2838.25 -250,2827.75 -256.85,2827.75 -280,2804.6 -280,2790 -285,2785 U1.3@-319.61,2785 ; v1@-260.98,2900.04 ccw(c-244.02,2900.04) -256.01,2888.05 ; v1@-256.98,2900.04 ccw(c-230.36,2900.04) -249.18,2881.22 ; U1.3@-319.61,2785 U1.3@-320,2784.61 U1.3@-319.61,2785
  Bottom Layer w4: R20.2@-295.06,2891.24 cw(c-285.98,2882.16) -285.98,2895 cw(c-285.98,2907.84) R20.2@-295.06,2898.76 ; R20.2@-292.23,2888.41 cw(c-276.32,2872.5) -276.32,2895 cw(c-276.32,2917.5) R20.2@-292.23,2901.59 ; R20.2@-289.92,2895 ccw(c-289.92,2920.84) v1@-270.59,2903.69 ; -281.02,2895 ccw(c-281.02,2912.95) v1@-267.6,2901.04 ; -277.24,2895 cw(c-277.24,2889.28) v1@-273.19,2893.32 ; v1@-273.58,2906.35 cw(c-298.82,2928.74) R20.2@-298.82,2895 -271.52,2895 v1(-266.48,2900.04)
NetR23_2: R23.2 U1.22 | length 289
  Top Layer w4: U1.22@-79.84,2784.61 12.42,2784.61 v1(61.52,2833.71) ; U1.22@-60.1,2781.01 cw(c-51.42,2772.33) -51.42,2784.61 cw(c-51.42,2796.89) U1.22@-60.1,2788.2 ; v1@52.02,2833.71 cw(c29.09,2833.71) 45.31,2817.49 cw(c61.52,2801.27) v1@61.52,2824.21 ; v1@56.02,2833.71 cw(c42.75,2833.71) 52.14,2824.32 cw(c61.52,2814.93) v1@61.52,2828.21
  Bottom Layer w4: v1(61.52,2833.71) 72.82,2845 ; R23.2@80.71,2840.4 ccw(c72.82,2835.92) 72.82,2845 ; R23.2@80.71,2849.6 cw(c72.82,2854.08) 72.82,2845 ; R23.2@88.82,2845 72.82,2845
NetR24_2: R24.2 U1.23 | length 452.8
  Top Layer w4: U1.23@-79.84,2809.8 9.8,2809.8 48.52,2848.52 v1(48.52,2925.71) ; U1.23@-60.1,2806.21 cw(c-51.42,2797.52) -51.42,2809.8 cw(c-51.42,2822.08) U1.23@-60.1,2813.4 ; v1@41.81,2918.99 cw(c25.59,2902.77) 48.52,2902.77 cw(c71.46,2902.77) v1@55.24,2918.99 ; v1@44.64,2921.82 cw(c35.25,2912.43) 48.52,2912.43 cw(c61.8,2912.43) v1@52.41,2921.82
  Bottom Layer w4: v1(48.52,2925.71) 67.82,2945 ; v1@48.52,2931.21 ccw(c48.52,2944.49) 57.91,2935.1 ccw(c67.3,2925.71) v1@54.02,2925.71 ; v1@48.52,2935.21 ccw(c48.52,2958.14) 64.74,2941.93 ccw(c80.96,2925.71) v1@58.02,2925.71 ; R24.2@81.91,2938.75 ccw(c67.82,2925.99) 67.82,2945 ; R24.2@81.91,2951.25 cw(c67.82,2964.01) 67.82,2945 ; R24.2@84.88,2941.43 ccw(c76.83,2934.15) 76.83,2945 ccw(c76.83,2955.85) R24.2@84.88,2948.57 ; R24.2@88.82,2945 67.82,2945
NetR31_1: R31.1 U3.8 | length 870.4
  MidLayer2 w4: v1(4240.19,1050.04) 4265.19,1075.04 4265.19,1233.37 4274.52,1242.71 4320,1242.71 4327,1235.71 v1(4462.86,1235.71) ; v1@4240.19,1055.54 ccw(c4240.19,1068.82) 4249.58,1059.43 ccw(c4258.97,1050.04) v1@4245.69,1050.04 ; v1@4240.19,1059.54 ccw(c4240.19,1082.48) 4256.41,1066.26 ccw(c4272.63,1050.04) v1@4249.69,1050.04 ; v1@4456.14,1228.99 ccw(c4439.92,1212.77) 4439.92,1235.71 ccw(c4439.92,1258.64) v1@4456.14,1242.43 ; v1@4458.97,1231.82 ccw(c4449.58,1222.43) 4449.58,1235.71 ccw(c4449.58,1248.99) v1@4458.97,1239.6
  Bottom Layer w4: U3.8@4076.5,1046.46 4118.52,1046.46 4122.11,1050.04 v1(4240.19,1050.04) ; U3.8@4105.8,1043.63 cw(c4112.63,1036.8) 4112.63,1046.46 cw(c4112.63,1056.12) U3.8@4105.8,1049.29 ; v1@4233.47,1043.32 ccw(c4217.26,1027.11) 4217.26,1050.04 ccw(c4217.26,1072.98) v1@4233.47,1056.76 ; v1@4236.3,1046.15 ccw(c4226.91,1036.76) 4226.91,1050.04 ccw(c4226.91,1063.32) v1@4236.3,1053.93 ; v1@4462.86,1226.21 cw(c4462.86,1203.27) 4479.07,1219.49 cw(c4495.29,1235.71) v1@4472.36,1235.71 ; v1@4462.86,1230.21 cw(c4462.86,1216.93) 4472.25,1226.32 cw(c4481.64,1235.71) v1@4468.36,1235.71 ; v1(4462.86,1235.71) 4480,1218.56 ; R31.1@4474.84,1208.94 ccw(c4468.45,1218.56) 4480,1218.56 ; R31.1@4480,1201.18 4480,1218.56 ; R31.1@4485.16,1208.94 cw(c4491.55,1218.56) 4480,1218.56
NetR31_2: R31.2 R32.1 | length 173.7
  Bottom Layer w4: R32.1@4473.41,1102.77 ccw(c4457.5,1118.68) 4480,1118.68 ccw(c4502.5,1118.68) R32.1@4486.59,1102.77 ; R31.2@4473.41,1152.23 cw(c4457.5,1136.32) 4480,1136.32 cw(c4502.5,1136.32) R31.2@4486.59,1152.23 ; R32.1@4476.24,1099.94 ccw(c4467.16,1109.02) 4480,1109.02 ccw(c4492.84,1109.02) R32.1@4483.76,1099.94 ; R31.2@4476.24,1155.06 cw(c4467.16,1145.98) 4480,1145.98 cw(c4492.84,1145.98) R31.2@4483.76,1155.06 ; R32.1@4480,1096.18 R31.2@4480,1158.82
NetR32_2: R32.2 R33.2 T1.4 | length 1338
  MidLayer1 w4: v1@4503.28,1393.28 cw(c4487.06,1377.06) 4510,1377.06 cw(c4532.93,1377.06) v1@4516.72,1393.28 ; v1@4506.11,1396.11 cw(c4496.72,1386.72) 4510,1386.72 cw(c4523.28,1386.72) v1@4513.89,1396.11 ; v1(4510,1400) 4510,1361.81 4498.19,1350 4498.19,1121.81 4530,1090 4530,1060 v1(4515,1045)
  Bottom Layer w4: R33.2@4421.59,956.08 ccw(c4405.68,971.99) 4428.18,971.99 ccw(c4450.68,971.99) R33.2@4434.77,956.08 ; R33.2@4424.42,953.25 ccw(c4415.34,962.33) 4428.18,962.33 ccw(c4441.02,962.33) R33.2@4431.94,953.25 ; R33.2@4428.18,949 4428.18,1048.18 4433.82,1053.82 R32.2@4480,1053.82 4488.82,1045 v1(4515,1045) ; v1@4508.28,1038.28 ccw(c4492.06,1022.06) 4492.06,1045 ccw(c4492.06,1067.93) v1@4508.28,1051.72 ; v1(4510,1400) 4550,1400 4565,1385 4960,1385 4968,1393 T1.4@4968,1466 ; v1@4511.11,1041.11 ccw(c4501.72,1031.72) 4501.72,1045 ccw(c4501.72,1058.28) v1@4511.11,1048.89 ; v1@4513.89,1396.11 cw(c4523.28,1386.72) 4523.28,1400 cw(c4523.28,1413.28) v1@4513.89,1403.89 ; v1@4516.72,1393.28 cw(c4532.93,1377.06) 4532.93,1400 cw(c4532.93,1422.93) v1@4516.72,1406.72
NetR33_1: R33.1 R34.1 | length 194.1
  Bottom Layer w4: R34.1@4318.52,939.19 cw(c4318.52,915.5) 4335.27,932.25 ; R34.1@4318.52,943.19 cw(c4318.52,929.16) R34.1@4328.44,939.08 ; R34.1@4318.52,949 4337.52,930 4366.82,930 R33.1@4385.82,949 ; R34.1@4323.84,948.51 ccw(c4335.49,948.51) R34.1@4327.25,940.27 ; R34.1@4327.84,948.51 ccw(c4349.15,948.51) 4334.08,933.44 ; 4369.07,932.25 cw(c4385.82,915.5) R33.1@4385.82,939.19 ; 4370.26,933.44 ccw(c4355.19,948.51) R33.1@4376.5,948.51 ; R33.1@4375.9,939.08 cw(c4385.82,929.16) R33.1@4385.82,943.19 ; R33.1@4377.09,940.27 ccw(c4368.85,948.51) R33.1@4380.5,948.51
NetR35_1: R35.1 R37.1 U3.1 | length 1181.6
  MidLayer1 w4: v1(4355,950) 4423.52,1018.52 v1(4423.52,1192.37) ; v1@4355,955.5 ccw(c4355,968.78) 4364.39,959.39 ccw(c4373.78,950) v1@4360.5,950 ; v1@4355,959.5 ccw(c4355,982.43) 4371.22,966.22 ccw(c4387.43,950) v1@4364.5,950 ; v1@4416.81,1185.66 cw(c4400.59,1169.44) 4423.52,1169.44 cw(c4446.46,1169.44) v1@4430.24,1185.66 ; v1@4419.64,1188.49 cw(c4410.25,1179.1) 4423.52,1179.1 cw(c4436.8,1179.1) v1@4427.41,1188.49
  MidLayer2 w4: v1(4240,950) v1(4355,950) ; v1@4243.89,946.11 cw(c4253.28,936.72) 4253.28,950 cw(c4253.28,963.28) v1@4243.89,953.89 ; v1@4246.72,943.28 cw(c4262.93,927.06) 4262.93,950 cw(c4262.93,972.93) v1@4246.72,956.72 ; v1@4348.28,943.28 ccw(c4332.06,927.06) 4332.06,950 ccw(c4332.06,972.93) v1@4348.28,956.72 ; v1@4351.11,946.11 ccw(c4341.72,936.72) 4341.72,950 ccw(c4341.72,963.28) v1@4351.11,953.89
  Bottom Layer w4: R37.1@4208.86,949 4209.86,950 v1(4240,950) ; R37.1@4212.62,945.73 cw(c4222.93,935.42) 4222.93,950 ; R37.1@4212.62,953.25 ccw(c4220.48,961.11) 4220.48,950 ; R37.1@4215.45,942.9 cw(c4232.58,925.77) v1@4232.58,950 ; R37.1@4215.45,956.08 ccw(c4230.13,970.76) v1@4230.13,950 ; v1@4233.28,943.28 ccw(c4217.06,927.06) 4217.06,950 ccw(c4217.06,972.93) v1@4233.28,956.72 ; v1@4236.11,946.11 ccw(c4226.72,936.72) 4226.72,950 ccw(c4226.72,963.28) v1@4236.11,953.89 ; U3.1@4295,1200 4340.19,1200 4341.37,1201.18 4414.72,1201.18 ; U3.1@4324.31,1197.17 cw(c4331.14,1190.34) 4331.14,1200 cw(c4331.14,1209.66) U3.1@4324.31,1202.83 ; 4379.33,1201.18 cw(c4379.33,1148.18) v1@4416.81,1185.66 ; R35.1@4387.92,1194.59 ccw(c4372.01,1178.68) 4372.01,1201.18 ccw(c4372.01,1223.68) R35.1@4387.92,1207.77 ; R35.1@4388.99,1201.18 cw(c4388.99,1157.84) v1@4419.64,1188.49 ; R35.1@4390.75,1197.42 ccw(c4381.67,1188.34) 4381.67,1201.18 ccw(c4381.67,1214.02) R35.1@4390.75,1204.94 ; R35.1@4398.64,1201.18 cw(c4398.64,1167.49) v1@4422.46,1191.31 ; R35.1@4401.23,1201.18 cw(c4401.23,1182.16) v1@4418.52,1190.08 ; 4407.47,1201.18 cw(c4407.47,1185.02) v1@4422.16,1191.75 ; 4408.3,1201.18 cw(c4408.3,1177.15) v1@4425.29,1194.14 ; 4413.7,1201.18 cw(c4413.7,1187.87) v1@4425.8,1193.42 ; v1@4414.89,1188.42 ccw(c4395,1179.31) R35.1@4395,1201.18 4414.72,1201.18 ; v1(4423.52,1192.37) 4414.72,1201.18
NetR35_2: R35.2 R38.2 U3.2 U3.3 | length 547.3
  Bottom Layer w4: 4261.86,1148.67 cw(c4294.26,1148.67) U3.2@4271.35,1171.58 ; 4261.86,1155.21 ccw(c4274.85,1155.21) U3.3@4265.7,1145.98 ; 4261.86,1158.33 cw(c4284.6,1158.33) U3.2@4268.52,1174.41 ; 4261.86,1164.81 ccw(c4284.37,1164.81) U3.3@4268.52,1148.82 ; 4261.86,1167.98 cw(c4274.95,1167.98) U3.2@4265.69,1177.24 ; U3.3@4271.34,1151.66 cw(c4293.89,1174.41) 4261.86,1174.41 ; U3.2@4295,1174.41 4261.86,1174.41 ; U3.3@4324.31,1145.99 cw(c4331.14,1139.16) 4331.14,1148.82 cw(c4331.14,1158.48) U3.3@4324.31,1151.65 ; R35.2@4387.92,1152.23 ccw(c4372.01,1136.32) 4372.01,1158.82 ccw(c4372.01,1181.32) R35.2@4387.92,1165.41 ; R38.2@4388.41,1102.77 ccw(c4372.5,1118.68) 4395,1118.68 ccw(c4417.5,1118.68) R38.2@4401.59,1102.77 ; R35.2@4388.41,1152.23 cw(c4372.5,1136.32) 4395,1136.32 cw(c4417.5,1136.32) R35.2@4401.59,1152.23 ; R35.2@4390.75,1155.06 ccw(c4381.67,1145.98) 4381.67,1158.82 ccw(c4381.67,1171.66) R35.2@4390.75,1162.58 ; R38.2@4391.24,1099.94 ccw(c4382.16,1109.02) 4395,1109.02 ccw(c4407.84,1109.02) R38.2@4398.76,1099.94 ; R35.2@4391.24,1155.06 cw(c4382.16,1145.98) 4395,1145.98 cw(c4407.84,1145.98) R35.2@4398.76,1155.06 ; R38.2@4395,1096.18 R35.2@4395,1158.82 4351.63,1158.82 4341.64,1148.82 U3.3@4295,1148.82 4261.86,1148.82 4261.86,1174.41
NetR40_1: R40.1 U4.4 | length 855.4
  MidLayer1 w4: v1@7865.19,2482.21 cw(c7865.19,2459.27) 7881.41,2475.49 cw(c7897.63,2491.71) v1@7874.69,2491.71 ; v1@7865.19,2486.21 cw(c7865.19,2472.93) 7874.58,2482.32 cw(c7883.97,2491.71) v1@7870.69,2491.71 ; v1(7865.19,2491.71) 7940.19,2416.71 7940.19,2293.04 7974.86,2258.37 7974.86,2109.86 7956.71,2091.71 v1(7873.52,2091.71) ; v1@7877.41,2087.82 cw(c7886.8,2078.43) 7886.8,2091.71 cw(c7886.8,2104.99) v1@7877.41,2095.6 ; v1@7880.24,2084.99 cw(c7896.46,2068.77) 7896.46,2091.71 cw(c7896.46,2114.64) v1@7880.24,2098.43
  Bottom Layer w4: v1@7858.47,2484.99 cw(c7842.26,2468.77) 7865.19,2468.77 cw(c7888.13,2468.77) v1@7871.91,2484.99 ; v1@7861.3,2487.82 cw(c7851.91,2478.43) 7865.19,2478.43 cw(c7878.47,2478.43) v1@7869.08,2487.82 ; v1(7865.19,2491.71) 7865.19,2463.45 7873.52,2455.12 ; v1(7873.52,2091.71) 7887.82,2091.71 7889.52,2090 ; U4.4@7884.62,2449.41 ccw(c7873.52,2441.48) 7873.52,2455.12 ; U4.4@7884.62,2460.82 cw(c7873.53,2468.75) 7873.53,2455.12 ; U4.4@7892.6,2455.12 7873.52,2455.12 ; R40.1@7901.52,2084.21 ccw(c7889.53,2074.69) 7889.53,2090 ; R40.1@7901.52,2095.79 cw(c7889.53,2105.31) 7889.53,2090 ; R40.1@7908.82,2090 7889.52,2090
NetR53_1: R53.1 R56.2 | length 90.3
  Bottom Layer w12: R53.1@2275.06,5734.25 ccw(c2265.98,5743.33) 2278.82,5743.33 ccw(c2291.66,5743.33) R53.1@2282.58,5734.25 ; R56.2@2275.06,5775.75 cw(c2265.98,5766.67) 2278.82,5766.67 cw(c2291.66,5766.67) R56.2@2282.58,5775.75 ; R53.1@2278.82,5730 R56.2@2278.82,5780
NetR53_2: R53.2 U5.28 | length 96.8
  Bottom Layer w12: U5.28@2311.65,5657.32 2311.65,5705.47 2321.18,5715 R53.2@2321.18,5730 ; R53.2@2317.42,5725.75 cw(c2308.34,5716.67) 2321.18,5716.67 cw(c2334.02,5716.67) R53.2@2324.94,5725.75
NetR98_1: R98.1 U45.3 | length 205.1
  Bottom Layer w4: U45.3@-202.85,2063.31 -202.85,2130.52 -183.68,2149.69 R98.1@-183.68,2205 ; R98.1@-190.27,2197.92 cw(c-206.18,2182.01) -183.68,2182.01 cw(c-161.18,2182.01) R98.1@-177.09,2197.92 ; R98.1@-187.44,2200.75 cw(c-196.52,2191.67) -183.68,2191.67 cw(c-170.84,2191.67) R98.1@-179.92,2200.75
NetR110_2: R110.2 U18.5 | length 169.8
  Bottom Layer w4: U18.5@7447.24,495 7472,495 ; U18.5@7463.74,489.84 cw(c7472,485.81) 7472,495 ; U18.5@7463.74,500.16 ccw(c7472,504.19) 7472,495 ; 7477.07,451.75 ccw(c7493.82,468.5) R110.2@7493.82,444.81 ; 7478.26,450.56 cw(c7463.19,435.49) R110.2@7484.5,435.49 ; R110.2@7483.9,444.92 ccw(c7493.82,454.84) R110.2@7493.82,440.81 ; R110.2@7485.09,443.73 cw(c7476.85,435.49) R110.2@7488.5,435.49 ; R110.2@7493.82,435 7475,453.82 7475,492 7472,495
NetR112_2: R112.2 U19.13 | length 375
  MidLayer2 w4: v1(7224.19,591.71) 7284.36,591.71 v5(7311.73,564.34) ; v1@7228.08,587.82 cw(c7237.47,578.43) 7237.47,591.71 cw(c7237.47,604.99) v1@7228.08,595.6 ; v1@7230.91,584.99 cw(c7247.13,568.77) 7247.13,591.71 cw(c7247.13,614.64) v1@7230.91,598.43 ; v5@7303.73,564.34 ccw(c7284.42,564.34) 7298.08,578 ccw(c7311.73,591.65) v5@7311.73,572.34
  Bottom Layer w4: R112.2@7199.94,591.24 cw(c7209.02,582.16) 7209.02,595 cw(c7209.02,607.84) R112.2@7199.94,598.76 ; R112.2@7202.77,588.41 cw(c7218.68,572.5) 7218.68,595 cw(c7218.68,617.5) R112.2@7202.77,601.59 ; R112.2@7204.94,595 cw(c7204.94,575.03) v1@7220.03,588.11 ; 7209.2,595 ccw(c7209.2,606.7) v1@7217.47,598.43 ; v1@7217.01,585.49 ccw(c7196.18,567.44) R112.2@7196.18,595 7220.9,595 v1(7224.19,591.71)
  Bottom Layer w8: v5@7307.49,568.58 ccw(c7297.25,578.82) 7311.73,578.82 ccw(c7326.22,578.82) v5@7315.97,568.58 ; v5(7311.73,564.34) U19.13@7311.73,595.67
NetR113_2: R113.2 U19.15 | length 254.1
  Bottom Layer w4: R113.2@7147.23,702.92 cw(c7131.32,687.01) 7153.82,687.01 cw(c7176.32,687.01) R113.2@7160.41,702.92 ; R113.2@7150.06,705.75 cw(c7140.98,696.67) 7153.82,696.67 cw(c7166.66,696.67) R113.2@7157.58,705.75 ; R113.2@7153.82,710 7153.82,650.08 7181.86,622.05 U19.15@7265.67,622.05 ; U19.15@7251.91,619.22 ccw(c7245.08,612.39) 7245.08,622.05 ccw(c7245.08,631.7) U19.15@7251.91,624.88
NetR114_2: R114.2 U19.16 | length 297.7
  Bottom Layer w8: R114.2@7153.82,812.19 cw(c7153.82,793.33) 7167.15,806.67 ; R114.2@7153.82,820 7175,798.82 7175,655 7188.27,641.73 U19.16@7265.67,641.73 ; R114.2@7161.14,819.51 ccw(c7177.62,819.51) 7165.97,807.85
NetR116_2: R116.2 U21.38 | length 260.3
  Bottom Layer w4: R116.2@4921.18,5740 4961.18,5780 5048.12,5780 5056.42,5771.71 U21.38@5056.42,5737.32 ; R116.2@4921.18,5745.81 ccw(c4921.18,5759.84) R116.2@4931.1,5749.92 ; R116.2@4921.18,5749.81 ccw(c4921.18,5773.5) 4937.93,5756.75 ; R116.2@4926.5,5740.49 cw(c4938.15,5740.49) R116.2@4929.91,5748.73 ; R116.2@4930.5,5740.49 cw(c4951.81,5740.49) 4936.74,5755.56 ; U21.38@5053.59,5763.68 ccw(c5046.76,5770.51) 5056.42,5770.51 ccw(c5066.07,5770.51) U21.38@5059.25,5763.68
NetR142_1: R142.1 U26.12 | length 688.2
  Top Layer w4: U26.12@-30.87,5000 40,5000 60,4980 86.82,4980 v1(106.86,5000.04) ; U26.12@6.71,4995.89 cw(c16.63,4985.97) 16.63,5000 cw(c16.63,5014.03) U26.12@6.71,5004.11 ; U26.12@9.54,4993.06 cw(c26.28,4976.31) 26.28,5000 cw(c26.28,5023.69) U26.12@9.54,5006.94 ; v1@97.36,5000.04 cw(c74.42,5000.04) 90.64,4983.82 cw(c106.86,4967.61) v1@106.86,4990.54 ; v1@101.36,5000.04 cw(c88.08,5000.04) 97.47,4990.65 cw(c106.86,4981.26) v1@106.86,4994.54
  MidLayer2 w4: v1@100.14,5006.76 ccw(c83.92,5022.98) 106.86,5022.98 ccw(c129.79,5022.98) v1@113.57,5006.76 ; v1@102.97,5003.93 ccw(c93.58,5013.32) 106.86,5013.32 ccw(c120.14,5013.32) v1@110.75,5003.93 ; v1(106.86,5000.04) 106.86,5176.86 125,5195 ; v1@119,5207.64 cw(c108.7,5195) 125,5195 ; v1@121.53,5210.74 cw(c115.56,5203.42) 125,5203.42 cw(c134.44,5203.42) v1@128.47,5210.74 ; v1(125,5215) 125,5195 ; v1@131,5207.64 ccw(c141.3,5195) 125,5195
  Bottom Layer w4: R142.1@108.64,5245.8 125,5229.44 v1(125,5215) ; R142.1@108.7,5235.99 cw(c108.84,5212.79) 125.25,5229.19 ; R142.1@108.67,5239.99 cw(c108.76,5226.24) R142.1@118.48,5235.96 ; R142.1@113.96,5245.3 ccw(c125.61,5245.3) R142.1@117.37,5237.06 ; R142.1@117.96,5245.3 ccw(c139.27,5245.3) 124.2,5230.24
NetR149_2: R149.2 U28.2 U29.5 | length 1233.7
  Top Layer w4: R149.2@369.59,5407.92 cw(c353.68,5392.01) 376.18,5392.01 cw(c398.68,5392.01) R149.2@382.77,5407.92 ; R149.2@372.42,5410.75 cw(c363.34,5401.67) 376.18,5401.67 cw(c389.02,5401.67) R149.2@379.94,5410.75 ; v1@378.28,5356.72 ccw(c362.06,5372.93) 385,5372.93 ccw(c407.93,5372.93) v1@391.72,5356.72 ; R149.2@379.94,5411.24 cw(c389.02,5402.16) 389.02,5415 cw(c389.02,5427.84) R149.2@379.94,5418.76 ; v1@381.11,5353.89 ccw(c371.72,5363.28) 385,5363.28 ccw(c398.28,5363.28) v1@388.89,5353.89 ; R149.2@382.77,5408.41 cw(c398.68,5392.5) 398.68,5415 cw(c398.68,5437.5) R149.2@382.77,5421.59 ; v1(385,5350) 385,5380 376.18,5388.82 R149.2@376.18,5415 421.54,5415 456.86,5379.68 U28.2@509.29,5379.69 ; U28.2@479,5376.86 ccw(c472.17,5370.03) 472.17,5379.68 ccw(c472.17,5389.34) U28.2@479,5382.51 ; U29.5@867.83,5354.41 880.59,5354.41 v1(905,5330) ; U29.5@876.69,5348.54 cw(c876.69,5324.94) 893.37,5341.63 ; U29.5@876.69,5352.54 cw(c876.69,5338.6) 886.55,5348.45 ; U29.5@882.57,5354.41 ccw(c887.34,5354.41) U29.5@883.96,5351.04 ; v1@895.5,5330 ccw(c872.56,5330) 888.78,5346.22 ccw(c905,5362.43) v1@905,5339.5 ; v1@899.5,5330 ccw(c886.22,5330) 895.61,5339.39 ccw(c905,5348.78) v1@905,5335.5
  MidLayer1 w4: v1(385,5350) 800,5350 865,5285 890,5285 905,5300 v1(905,5330) ; v1@388.89,5346.11 cw(c398.28,5336.72) 398.28,5350 cw(c398.28,5363.28) v1@388.89,5353.89 ; v1@391.72,5343.28 cw(c407.93,5327.06) 407.93,5350 cw(c407.93,5372.93) v1@391.72,5356.72 ; v1@898.28,5323.28 cw(c882.06,5307.06) 905,5307.06 cw(c927.93,5307.06) v1@911.72,5323.28 ; v1@901.11,5326.11 cw(c891.72,5316.72) 905,5316.72 cw(c918.28,5316.72) v1@908.89,5326.11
